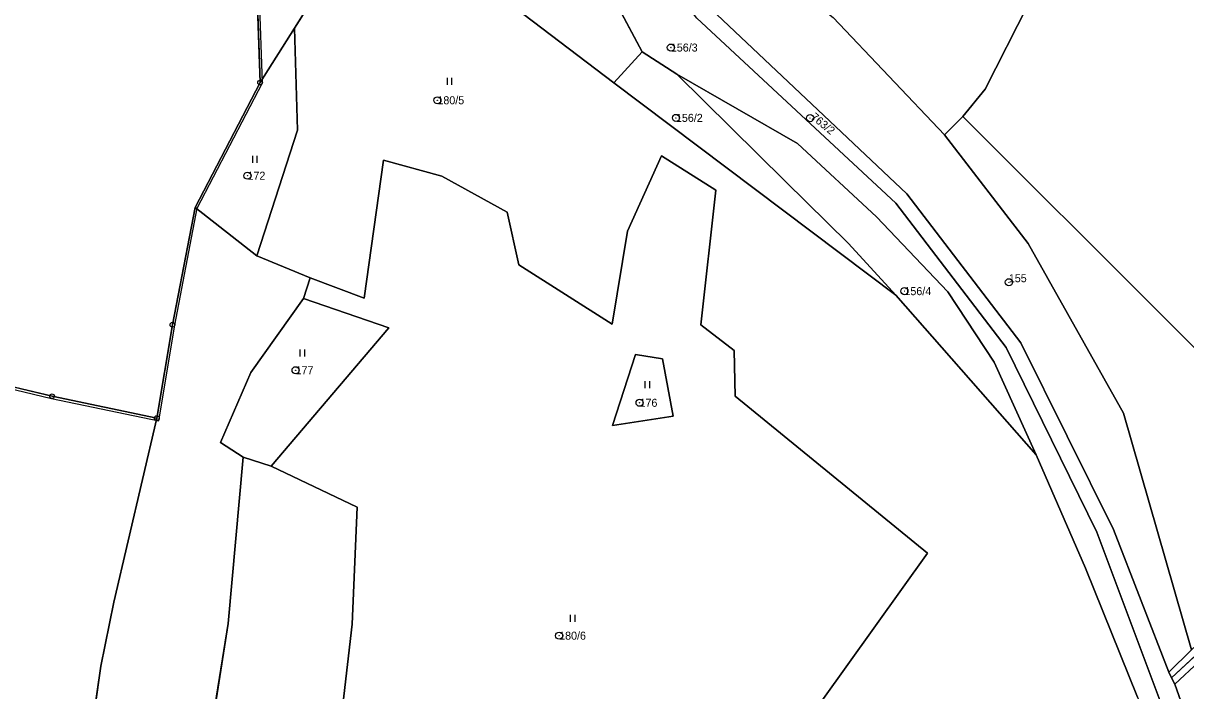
# Model space of a CAD drawing. Extents: x -652854 to -650068, y -1097661 to -1095417.
# Drawn here: x -651066.4 to -650819.6, y -1095750.2 to -1095608.5 of the extents above; entities that cross this region are included whole.
import ezdxf

# ---------------------------------------------------------------- set-up
doc = ezdxf.new("R2010")
doc.units = 0
for name, color, linetype in [('Definiční body parcel', 7, 'Continuous'), ('Geodetické body', 7, 'Continuous'), ('Hranice obcí', 7, 'Continuous'), ('Hranice parcel', 7, 'Continuous'), ('Obvody jako plochy', 7, 'Continuous'), ('Ostatní hranice', 7, 'Continuous'), ('Parcelní čísla', 7, 'Continuous'), ('Značky kultur', 7, 'Continuous')]:
    doc.layers.add(name, color=color, linetype=linetype)

msp = doc.modelspace()

# ---------------------------------------------------------------- linework, layer by layer
at = {"layer": 'Definiční body parcel'}
for centre, radius in [((-650928.93, -1095613.68), 0.75), ((-650928.93, -1095613.68), 0.0327), ((-650978.5, -1095624.87), 0.75), ((-650978.5, -1095624.87), 0.0327), ((-650927.85, -1095628.61), 0.75), ((-650927.85, -1095628.61), 0.0327), ((-650899.35, -1095628.67), 0.75), ((-650899.35, -1095628.67), 0.0327), ((-651018.83, -1095640.89), 0.75), ((-651018.83, -1095640.89), 0.0327), ((-650879.33, -1095665.4), 0.75), ((-650857.16, -1095663.5), 0.75), ((-650857.16, -1095663.5), 0.0327), ((-650879.33, -1095665.4), 0.0327), ((-651008.62, -1095682.19), 0.75), ((-651008.62, -1095682.19), 0.0327), ((-650935.58, -1095689.1), 0.75), ((-650935.58, -1095689.1), 0.0327), ((-650952.65, -1095738.55), 0.75), ((-650952.65, -1095738.55), 0.0327)]:
    msp.add_circle(centre, radius, dxfattribs=at)
at = {"layer": 'Geodetické body'}
for centre, radius in [((-651016.16, -1095621.12), 0.5), ((-651016.16, -1095621.12), 0.001), ((-651034.77, -1095672.54), 0.5), ((-651034.77, -1095672.54), 0.001), ((-651060.33, -1095687.71), 0.5), ((-651060.33, -1095687.71), 0.001), ((-651038.08, -1095692.34), 0.5), ((-651038.08, -1095692.34), 0.001)]:
    msp.add_circle(centre, radius, dxfattribs=at)
at = {"layer": 'Hranice obcí'}
for p, q in [((-651016.16, -1095621.12), (-651018.95, -1095537.44)), ((-651029.96, -1095647.61), (-651016.16, -1095621.12)), ((-651034.77, -1095672.54), (-651029.96, -1095647.61)), ((-651038.08, -1095692.34), (-651034.77, -1095672.54)), ((-651085.24, -1095681.81), (-651060.33, -1095687.71)), ((-651060.33, -1095687.71), (-651038.08, -1095692.34))]:
    msp.add_line(p, q, dxfattribs=at)
at = {"layer": 'Hranice parcel'}
for p, q in [((-650988.69, -1095584.93), (-650941.03, -1095621.17)), ((-650944.79, -1095596.25), (-650935.02, -1095614.61)), ((-651008.83, -1095609.57), (-651002.18, -1095598.99)), ((-650878.83, -1095644.72), (-650921.67, -1095604.35)), ((-650862.18, -1095622.48), (-650853.09, -1095604.56)), ((-650923.38, -1095607.47), (-650881.16, -1095646.75)), ((-650894.47, -1095607.28), (-650870.79, -1095632.18)), ((-651016.16, -1095621.12), (-651008.83, -1095609.57)), ((-651008.83, -1095609.57), (-651008.21, -1095631.2)), ((-650941.03, -1095621.17), (-650935.02, -1095614.61)), ((-650935.02, -1095614.61), (-650927.69, -1095619.32)), ((-650927.69, -1095619.32), (-650904.67, -1095642.05)), ((-650927.69, -1095619.32), (-650902.01, -1095634.04)), ((-650941.03, -1095621.17), (-650881.15, -1095666.23)), ((-650866.94, -1095628.35), (-650862.18, -1095622.48)), ((-650870.79, -1095632.18), (-650866.94, -1095628.35)), ((-650866.94, -1095628.35), (-650824.98, -1095670.21)), ((-651008.21, -1095631.2), (-651016.83, -1095657.9)), ((-650853.03, -1095655.29), (-650870.79, -1095632.18)), ((-650902.01, -1095634.04), (-650885.23, -1095649.63)), ((-650938.16, -1095652.63), (-650930.89, -1095636.7)), ((-650930.89, -1095636.7), (-650919.38, -1095643.96)), ((-650994.04, -1095666.89), (-650989.96, -1095637.59)), ((-650989.96, -1095637.59), (-650977.55, -1095640.98)), ((-650977.55, -1095640.98), (-650963.69, -1095648.62)), ((-650904.67, -1095642.05), (-650891.23, -1095655.26)), ((-650919.38, -1095643.96), (-650922.57, -1095672.56)), ((-650854.62, -1095676.4), (-650878.83, -1095644.72)), ((-650881.16, -1095646.75), (-650857.72, -1095677.34)), ((-651016.83, -1095657.9), (-651029.96, -1095647.61)), ((-650963.69, -1095648.62), (-650961.18, -1095659.78)), ((-650885.23, -1095649.63), (-650870.11, -1095665.52)), ((-650941.37, -1095672.44), (-650938.16, -1095652.63)), ((-650891.23, -1095655.26), (-650881.15, -1095666.23)), ((-650832.81, -1095691.31), (-650853.03, -1095655.29)), ((-651016.83, -1095657.9), (-651005.5, -1095662.57)), ((-650961.18, -1095659.78), (-650941.37, -1095672.44)), ((-651005.5, -1095662.57), (-651006.94, -1095666.93)), ((-651005.5, -1095662.57), (-650994.04, -1095666.89)), ((-651006.94, -1095666.93), (-651018.1, -1095682.66)), ((-650988.82, -1095673.17), (-651006.94, -1095666.93)), ((-650881.15, -1095666.23), (-650851.38, -1095700.16)), ((-650870.11, -1095665.52), (-650860.26, -1095680.47)), ((-650824.98, -1095670.21), (-650789.28, -1095705.95)), ((-651013.78, -1095702.59), (-650988.82, -1095673.17)), ((-650922.57, -1095672.56), (-650915.52, -1095678.01)), ((-650834.91, -1095715.97), (-650854.62, -1095676.4)), ((-650936.43, -1095678.82), (-650941.35, -1095693.94)), ((-650930.73, -1095679.78), (-650936.43, -1095678.82)), ((-650915.52, -1095678.01), (-650915.3, -1095687.7)), ((-650857.72, -1095677.34), (-650838.48, -1095716.55)), ((-650928.45, -1095691.96), (-650930.73, -1095679.78)), ((-650860.26, -1095680.47), (-650851.38, -1095700.16)), ((-651018.1, -1095682.66), (-651024.58, -1095697.54)), ((-650915.3, -1095687.7), (-650874.43, -1095721.03)), ((-650818.36, -1095741.53), (-650832.81, -1095691.31)), ((-651047.21, -1095731.45), (-651038.08, -1095692.34)), ((-650941.35, -1095693.94), (-650928.45, -1095691.96)), ((-651024.58, -1095697.54), (-651019.78, -1095700.67)), ((-651019.78, -1095700.67), (-651022.9, -1095735.99)), ((-651019.78, -1095700.67), (-651013.78, -1095702.59)), ((-650851.38, -1095700.16), (-650840.85, -1095724.23)), ((-650995.52, -1095711.24), (-651013.78, -1095702.59)), ((-650996.59, -1095736.08), (-650995.52, -1095711.24)), ((-650823.21, -1095746.31), (-650834.91, -1095715.97)), ((-650838.48, -1095716.55), (-650825.13, -1095752.26)), ((-650874.43, -1095721.03), (-650896.84, -1095752.39)), ((-650840.85, -1095724.23), (-650829.85, -1095751.61)), ((-651049.97, -1095744.99), (-651047.21, -1095731.45)), ((-651022.9, -1095735.99), (-651030.34, -1095782.27)), ((-651002.9, -1095790.53), (-650996.59, -1095736.08)), ((-650808.36, -1095734.29), (-650822.61, -1095747.49)), ((-650818.36, -1095741.53), (-650823.21, -1095746.31)), ((-651055.01, -1095780.49), (-651049.97, -1095744.99)), ((-650821.9, -1095748.87), (-650816.71, -1095744.03)), ((-650823.21, -1095746.31), (-650822.61, -1095747.49)), ((-650822.61, -1095747.49), (-650821.9, -1095748.87)), ((-650820.19, -1095753.68), (-650821.9, -1095748.87))]:
    msp.add_line(p, q, dxfattribs=at)
at = {"layer": 'Obvody jako plochy'}
for points in [[(-650960.55, -1095551.05), (-650930.04, -1095580.18), (-650916.96, -1095589.5), (-650894.47, -1095607.28), (-650870.79, -1095632.18), (-650866.94, -1095628.35), (-650862.18, -1095622.48), (-650853.09, -1095604.56), (-650972.25, -1095520.85), (-650975.04, -1095521.11)], [(-650942.18, -1095588.83), (-650944.79, -1095596.25), (-650935.02, -1095614.61), (-650927.69, -1095619.32), (-650902.01, -1095634.04), (-650885.23, -1095649.63), (-650870.11, -1095665.52), (-650860.26, -1095680.47), (-650851.38, -1095700.16), (-650840.85, -1095724.23), (-650829.85, -1095751.61), (-650828.36, -1095754.97), (-650825.74, -1095811.08), (-650821.45, -1095812.61), (-650825.13, -1095752.26), (-650838.48, -1095716.55), (-650857.72, -1095677.34), (-650881.16, -1095646.75), (-650923.38, -1095607.47), (-650940.04, -1095585.42)], [(-650755.12, -1095669), (-650752.15, -1095665.53), (-650793.83, -1095624.33), (-650833.99, -1095584.78), (-650835.5, -1095586.31), (-650845.17, -1095596.13), (-650853.09, -1095604.56), (-650862.18, -1095622.48), (-650866.94, -1095628.35), (-650824.98, -1095670.21), (-650789.28, -1095705.95), (-650768.91, -1095684.86), (-650761.09, -1095680.61)], [(-651016.16, -1095621.12), (-651029.96, -1095647.61), (-651016.83, -1095657.9), (-651008.21, -1095631.2), (-651008.83, -1095609.57)], [(-650941.03, -1095621.17), (-650881.15, -1095666.23), (-650891.23, -1095655.26), (-650904.67, -1095642.05), (-650927.69, -1095619.32), (-650935.02, -1095614.61)], [(-650881.15, -1095666.23), (-650851.38, -1095700.16), (-650860.26, -1095680.47), (-650870.11, -1095665.52), (-650885.23, -1095649.63), (-650902.01, -1095634.04), (-650927.69, -1095619.32), (-650904.67, -1095642.05), (-650891.23, -1095655.26)], [(-650853.03, -1095655.29), (-650832.81, -1095691.31), (-650818.36, -1095741.53), (-650809.03, -1095732.92), (-650789.28, -1095705.95), (-650824.98, -1095670.21), (-650866.94, -1095628.35), (-650870.79, -1095632.18)], [(-651063.2, -1095851.8), (-651051.52, -1095853.78), (-651038.89, -1095851.2), (-651039.82, -1095847.91), (-651038.5, -1095847.07), (-651030.34, -1095782.27), (-651022.9, -1095735.99), (-651019.78, -1095700.67), (-651024.58, -1095697.54), (-651018.1, -1095682.66), (-651006.94, -1095666.93), (-651005.5, -1095662.57), (-651016.83, -1095657.9), (-651029.96, -1095647.61), (-651034.77, -1095672.54), (-651038.08, -1095692.34), (-651047.21, -1095731.45), (-651049.97, -1095744.99), (-651055.01, -1095780.49), (-651058.73, -1095802.33), (-651060.77, -1095828.02)], [(-651006.94, -1095666.93), (-651018.1, -1095682.66), (-651024.58, -1095697.54), (-651019.78, -1095700.67), (-651013.78, -1095702.59), (-650988.82, -1095673.17)], [(-650936.43, -1095678.82), (-650941.35, -1095693.94), (-650928.45, -1095691.96), (-650930.73, -1095679.78)], [(-650936.43, -1095678.82), (-650930.73, -1095679.78), (-650928.45, -1095691.96), (-650941.35, -1095693.94)], [(-651112.39, -1095768.57), (-651117.53, -1095804.25), (-651096.89, -1095800.65), (-651095.09, -1095794.17), (-651070.25, -1095802.81), (-651070.13, -1095820.09), (-651070.86, -1095852.7), (-651063.2, -1095851.8), (-651060.77, -1095828.02), (-651058.73, -1095802.33), (-651055.01, -1095780.49), (-651049.97, -1095744.99), (-651047.21, -1095731.45), (-651038.08, -1095692.34), (-651060.33, -1095687.71), (-651085.24, -1095681.81), (-651097.08, -1095681.29), (-651101.52, -1095702.76), (-651104.09, -1095719.7), (-651109.22, -1095754.65)], [(-650767.79, -1095686.92), (-650768.34, -1095685.9), (-650788.14, -1095706.99), (-650808.36, -1095734.29), (-650822.61, -1095747.49), (-650821.9, -1095748.87), (-650816.71, -1095744.03), (-650807.71, -1095735.72), (-650786.76, -1095707.77)], [(-651019.78, -1095700.67), (-651022.9, -1095735.99), (-651030.34, -1095782.27), (-651038.5, -1095847.07), (-651030.08, -1095842.4), (-651022.74, -1095844.69), (-651007.42, -1095842.39), (-651002.9, -1095790.53), (-650996.59, -1095736.08), (-650995.52, -1095711.24), (-651013.78, -1095702.59)], [(-650823.21, -1095746.31), (-650822.61, -1095747.49), (-650808.36, -1095734.29), (-650788.14, -1095706.99), (-650789.28, -1095705.95), (-650809.03, -1095732.92), (-650818.36, -1095741.53)]]:
    msp.add_lwpolyline(points, close=True, dxfattribs=at)
for points in [[(-651018.95, -1095537.44), (-651016.16, -1095621.12), (-651008.83, -1095609.57), (-651002.18, -1095598.99)], [(-650988.69, -1095584.93), (-650941.03, -1095621.17), (-650935.02, -1095614.61), (-650944.79, -1095596.25)], [(-650829.85, -1095751.61), (-650840.85, -1095724.23), (-650851.38, -1095700.16), (-650881.15, -1095666.23), (-650941.03, -1095621.17), (-650988.69, -1095584.93)], [(-651002.18, -1095598.99), (-651008.83, -1095609.57), (-651008.21, -1095631.2), (-651016.83, -1095657.9), (-651005.5, -1095662.57), (-650994.04, -1095666.89), (-650989.96, -1095637.59), (-650977.55, -1095640.98), (-650963.69, -1095648.62), (-650961.18, -1095659.78), (-650941.37, -1095672.44), (-650938.16, -1095652.63), (-650930.89, -1095636.7), (-650919.38, -1095643.96), (-650922.57, -1095672.56), (-650915.52, -1095678.01), (-650915.3, -1095687.7), (-650874.43, -1095721.03), (-650896.84, -1095752.39)], [(-650921.67, -1095604.35), (-650878.83, -1095644.72), (-650854.62, -1095676.4), (-650834.91, -1095715.97), (-650823.21, -1095746.31), (-650818.36, -1095741.53), (-650832.81, -1095691.31), (-650853.03, -1095655.29), (-650870.79, -1095632.18), (-650894.47, -1095607.28)], [(-650816.69, -1095813.37), (-650820.19, -1095753.68), (-650821.9, -1095748.87), (-650822.61, -1095747.49), (-650823.21, -1095746.31), (-650834.91, -1095715.97), (-650854.62, -1095676.4), (-650878.83, -1095644.72), (-650921.67, -1095604.35)], [(-650923.38, -1095607.47), (-650881.16, -1095646.75), (-650857.72, -1095677.34), (-650838.48, -1095716.55), (-650825.13, -1095752.26), (-650821.45, -1095812.61), (-650822.33, -1095847.63), (-650818.61, -1095859.41)], [(-650896.84, -1095752.39), (-650874.43, -1095721.03), (-650915.3, -1095687.7), (-650915.52, -1095678.01), (-650922.57, -1095672.56), (-650919.38, -1095643.96), (-650930.89, -1095636.7), (-650938.16, -1095652.63), (-650941.37, -1095672.44), (-650961.18, -1095659.78), (-650963.69, -1095648.62), (-650977.55, -1095640.98), (-650989.96, -1095637.59), (-650994.04, -1095666.89), (-651005.5, -1095662.57), (-651006.94, -1095666.93), (-650988.82, -1095673.17), (-651013.78, -1095702.59), (-650995.52, -1095711.24), (-650996.59, -1095736.08), (-651002.9, -1095790.53)], [(-650816.71, -1095744.03), (-650821.9, -1095748.87), (-650820.19, -1095753.68), (-650816.69, -1095813.37)]]:
    msp.add_lwpolyline(points, dxfattribs=at)
at = {"layer": 'Ostatní hranice'}
for p, q in [((-651015.67, -1095621.16), (-651018.47, -1095537.15)), ((-651029.51, -1095647.78), (-651015.67, -1095621.16)), ((-651034.28, -1095672.62), (-651029.51, -1095647.78)), ((-651037.69, -1095692.91), (-651034.28, -1095672.62)), ((-651085.33, -1095682.28), (-651060.46, -1095688.18)), ((-651060.46, -1095688.18), (-651037.69, -1095692.91))]:
    msp.add_line(p, q, dxfattribs=at)
at = {"layer": 'Značky kultur'}
for p, q in [((-650976.457, -1095620.085), (-650976.457, -1095621.585)), ((-650975.435, -1095621.585), (-650975.435, -1095620.085)), ((-651017.797, -1095636.635), (-651017.797, -1095638.135)), ((-651016.775, -1095638.135), (-651016.775, -1095636.635)), ((-651007.687, -1095677.755), (-651007.687, -1095679.255)), ((-651006.665, -1095679.255), (-651006.665, -1095677.755)), ((-650934.447, -1095684.485), (-650934.447, -1095685.985)), ((-650933.425, -1095685.985), (-650933.425, -1095684.485)), ((-650950.297, -1095734.115), (-650950.297, -1095735.615)), ((-650949.275, -1095735.615), (-650949.275, -1095734.115))]:
    msp.add_line(p, q, dxfattribs=at)

# ---------------------------------------------------------------- texts
at = {"layer": 'Parcelní čísla'}
for s, p in [('156/3', (-650928.93, -1095614.53)), ('180/5', (-650978.5, -1095625.72)), ('156/2', (-650927.85, -1095629.46)), ('172', (-651018.83, -1095641.74)), ('155', (-650857.16, -1095663.5)), ('156/4', (-650879.33, -1095666.25)), ('177', (-651008.62, -1095683.04)), ('176', (-650935.58, -1095689.95)), ('180/6', (-650952.65, -1095739.4))]:
    msp.add_text(s, height=1.7, dxfattribs=at).set_placement(p)
msp.add_text('763/2', height=1.7, rotation=320.364, dxfattribs=at).set_placement((-650899.35, -1095628.67))

doc.saveas('drawing.dxf')
